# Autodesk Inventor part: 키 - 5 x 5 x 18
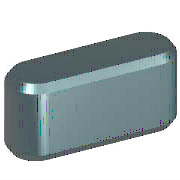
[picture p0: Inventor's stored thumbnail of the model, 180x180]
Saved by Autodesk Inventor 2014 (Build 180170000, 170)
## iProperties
Created: 2012-02
Part Number: 키 - 5 x 5 x 18
Material: 강철, 연강
Description: 키 및 해당 키홈
Document SubType Name: Modeling
Standard: KS B 1311
Designer: mduedu
Standards Organization: KS
Language: ko-KR
Size Designation: 5 x 5 x 18
Categories: <MemberInstance><Categories><Category DisplayName="샤프트 부품" InternalName="7f7aeb1f-a693-4053-b835-cee3144e0d98" Mnemonic="SHFT"><Category DisplayName="키" Interna
Density: 7.86 g/cm^3
Mass: 3.27476 g
Surface Area: 3.57848 cm^2
Volume: 0.416636 cm^3
Appearance: 파란색 - 벽 페인트 - 광택
IsCustomPart: 1
Author: mduedu
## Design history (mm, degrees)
workplane "Work Plane1"
workplane "Work Plane2"
sketch "스케치1"
  geometry: L1 (2.5, 2.5)-(15.5, 2.5); L2 (15.5, -2.5)-(2.5, -2.5); L3 (0, 9.4)-(0, -7.4) reference; L4 (-5, 0)-(30, 0) reference; L5 (18, 0)-(18, 7); A1 r 2.5 centre (2.5, 0) between (2.5, 2.5) and (2.5, -2.5); A2 r 2.5 centre (15.5, 0) between (15.5, -2.5) and (15.5, 2.5)
  constraints: 6 end point, 5 point on circle, 4 tangent, 3 point on line, 2 centre point, 1 horizontal, 1 parallel, 1 perpendicular
  dimensions: "d0" = 2.5 radius of A1 (= 0.5 x PB); "d13" = 2.5 radius of A2 (= 0.5 x PB); "d14" = 18 distance between parallel lines of L5 L3 (= NLG)
extrude "본체1" new body sketch "스케치1" taper "d3" = 0 deg; stored distance "d4" = 10
workplane "Work Plane3"
body "Solid1"
chamfer "모따기1" distance "d8" = 0.4 (= PHH); stored, may be unused: second distance "d9" = 0.4 (= PHH), angle "d15" = 45 deg
other parameters: "d1" = -3 (= -PNT), "d2" = 2 (= PH - PNT), "NLG" = 18 [user parameter; used in 3 equation terms], "PB" = 5 [user parameter; used in 2 equation terms], "PNT" = 3 [user parameter; used in 2 equation terms], "PH" = 5 [user parameter; used in 1 equation term], "PHH" = 0.4 [user parameter; used in 2 equation terms], "d10" = 0, "d16" = 0, "d17" = 0, "d18" = 0, "WDMIN" = 12 [user parameter], "PLB2" = 18 (= NLG) [user parameter], "WDMAX" = 17 [user parameter], "PLB1" = 18 (= NLG) [user parameter], "RR" = 0.16 [user parameter], "PUEB" = 2.3 [user parameter]
